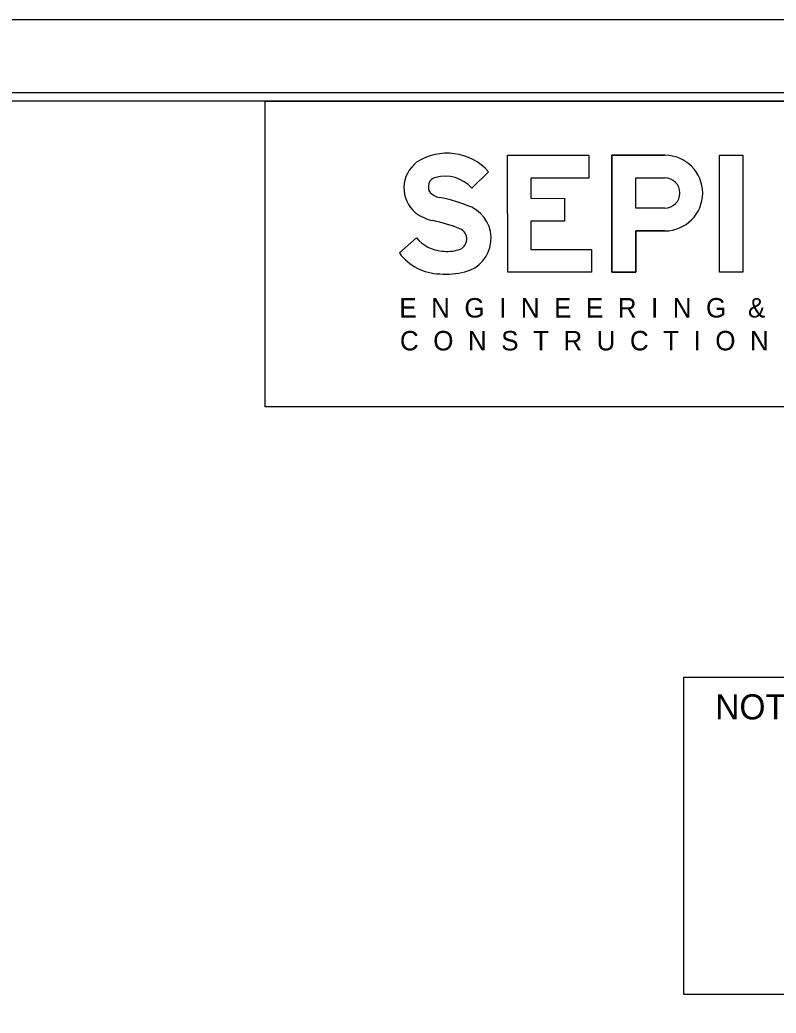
# Model space of a CAD drawing. Extents: x 2137858 to 2138172, y 2136084 to 2136289.
# Drawn here: x 2138065.4 to 2138108.7, y 2136232.1 to 2136289 of the extents above; entities that cross this region are included whole.
import ezdxf

# ---------------------------------------------------------------- set-up
doc = ezdxf.new("R2010")
doc.units = 0
for name, color, linetype in [('Default', 7, 'Continuous'), ('Old_Level_2', 7, 'Continuous'), ('Old_Level_21', 7, 'Continuous'), ('Old_Level_58', 7, 'Continuous'), ('Old_Level_61', 7, 'Continuous'), ('Sheet Cutting Line CELL', 7, 'Continuous'), ('Sheet Plot Border Inside CELL', 7, 'Continuous'), ('Sheet Plot Border Outside CELL', 7, 'Continuous'), ('Sheet Typical CELL', 7, 'Continuous')]:
    doc.layers.add(name, color=color, linetype=linetype)

msp = doc.modelspace()

# ---------------------------------------------------------------- linework, layer by layer
at = {"layer": 'Default'}
msp.add_lwpolyline([(2138167.466, 2136251.307), (2138103.421, 2136251.307), (2138103.421, 2136233.162), (2138167.466, 2136233.162)], close=True, dxfattribs=at)
at = {"layer": 'Old_Level_58'}
msp.add_lwpolyline([(2138079.453, 2136284.339), (2138131.966, 2136284.339), (2138131.966, 2136266.833), (2138079.453, 2136266.833)], close=True, dxfattribs=at)
at = {"layer": 'Old_Level_61'}
for p, q in [((2138093.347, 2136281.246), (2138098.003, 2136281.247)), ((2138093.348, 2136274.54), (2138093.347, 2136281.246)), ((2138098.003, 2136281.247), (2138098.003, 2136279.936)), ((2138102.354, 2136281.248), (2138099.324, 2136281.247)), ((2138105.478, 2136281.248), (2138106.82, 2136281.248)), ((2138105.479, 2136274.542), (2138105.478, 2136281.248)), ((2138106.82, 2136281.248), (2138106.821, 2136274.542)), ((2138092.256, 2136280.303), (2138091.289, 2136279.361)), ((2138098.003, 2136279.936), (2138094.683, 2136279.935)), ((2138094.683, 2136279.935), (2138094.683, 2136278.777)), ((2138094.683, 2136278.777), (2138096.603, 2136278.778)), ((2138096.603, 2136278.778), (2138096.604, 2136277.475)), ((2138102.354, 2136278.219), (2138100.692, 2136278.219)), ((2138096.604, 2136277.475), (2138094.684, 2136277.475)), ((2138094.684, 2136277.475), (2138094.684, 2136275.846)), ((2138087.149, 2136275.645), (2138088.122, 2136276.513)), ((2138094.684, 2136275.846), (2138098.155, 2136275.847)), ((2138098.155, 2136275.847), (2138098.155, 2136274.541)), ((2138098.155, 2136274.541), (2138093.348, 2136274.54)), ((2138106.821, 2136274.542), (2138105.479, 2136274.542))]:
    msp.add_line(p, q, dxfattribs=at)
for points in [[(2138099.324, 2136281.247), (2138102.354, 2136281.248)], [(2138102.354, 2136276.911), (2138100.692, 2136276.911), (2138100.693, 2136274.541), (2138099.325, 2136274.541), (2138099.324, 2136281.247)], [(2138099.324, 2136281.247), (2138099.325, 2136274.541), (2138100.693, 2136274.541), (2138100.692, 2136276.911), (2138102.354, 2136276.911)], [(2138100.692, 2136278.219), (2138100.692, 2136279.946), (2138102.354, 2136279.946)], [(2138100.692, 2136278.219), (2138100.692, 2136279.946), (2138102.354, 2136279.946)], [(2138102.354, 2136278.219), (2138100.692, 2136278.219)]]:
    msp.add_lwpolyline(points, dxfattribs=at)
for centre, radius, start, end in [((2138089.874, 2136278.148), 3.212, 42.1327, 122.9781), ((2138102.354, 2136279.079), 2.168, 270.0085, 90.0085), ((2138102.354, 2136279.079), 2.168, 270.0085, 90.0085), ((2138089.265, 2136279.371), 1.861, 127.737, 229.6653), ((2138089.353, 2136279.437), 0.555, 103.531, 215.5148), ((2138089.76, 2136278.002), 2.046, 41.6206, 105.1978), ((2138102.354, 2136279.083), 0.863, 270.0085, 90.0085), ((2138102.354, 2136279.083), 0.863, 270.0085, 90.0085), ((2138089.655, 2136279.863), 1.062, 224.8336, 256.8488), ((2138087.702, 2136269.698), 9.29, 67.2047, 79.3861), ((2138090.42, 2136276.487), 1.982, 283.8987, 63.5916), ((2138089.66, 2136280.156), 2.724, 234.0275, 257.3508), ((2138087.503, 2136269.424), 8.224, 67.7856, 79.0604), ((2138090.356, 2136276.445), 0.645, 286.1134, 66.6483), ((2138089.738, 2136277.832), 2.086, 219.2143, 265.7729), ((2138089.863, 2136278.329), 2.592, 263.8472, 285.0485), ((2138089.512, 2136277.385), 2.935, 216.3695, 269.0232), ((2138089.839, 2136278.875), 4.44, 265.1339, 283.7745)]:
    msp.add_arc(centre, radius, start, end, dxfattribs=at)
at = {"layer": 'Sheet Cutting Line CELL'}
msp.add_line((2138172.482, 2136289.006), (2137858.136, 2136289.006), dxfattribs=at)
at = {"layer": 'Sheet Plot Border Inside CELL'}
msp.add_lwpolyline([(2138171.642, 2136284.815), (2137860.562, 2136284.815), (2137860.562, 2136087.863), (2138171.642, 2136087.863)], close=True, dxfattribs=at)
at = {"layer": 'Sheet Plot Border Outside CELL'}
msp.add_lwpolyline([(2138172.482, 2136289.006), (2137858.136, 2136289.006), (2137858.136, 2136083.673), (2138172.482, 2136083.673)], close=True, dxfattribs=at)
at = {"layer": 'Sheet Typical CELL'}
msp.add_lwpolyline([(2138169.309, 2136284.339), (2137889.309, 2136284.339), (2137889.309, 2136088.339), (2138169.309, 2136088.339)], close=True, dxfattribs=at)

# ---------------------------------------------------------------- texts
at = {"layer": 'Old_Level_2'}
for s, p in [('E  N  G  I  N  E  E  R  I  N  G   &', (2138087.138, 2136271.944)), ('C  O  N  S  T  R  U  C  T  I  O  N', (2138087.174, 2136270.06))]:
    msp.add_text(s, height=1.11562, rotation=0.0086, dxfattribs=at).set_placement(p)
at = {"layer": 'Old_Level_21'}
msp.add_text('NOTES:  ', height=1.4354, dxfattribs=at).set_placement((2138105.241, 2136248.916))

doc.saveas('drawing.dxf')
